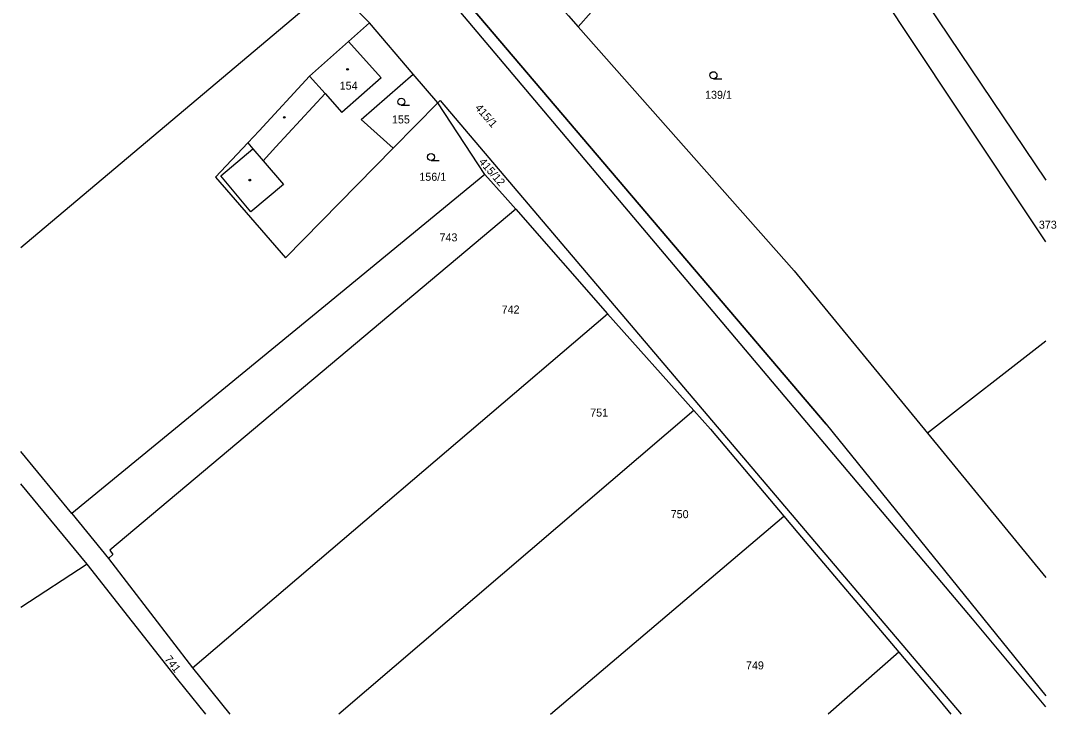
# Model space of a CAD drawing. Extents: x -504601 to -503665, y -1079870 to -1078626.
# Drawn here: x -504599.7 to -504379.8, y -1078928.2 to -1078780.8 of the extents above; entities that cross this region are included whole.
import ezdxf

# ---------------------------------------------------------------- set-up
doc = ezdxf.new("R2010")
doc.units = 0
for name, color, linetype in [('Hranice parcel', 7, 'Continuous'), ('Parcelní čísla', 7, 'Continuous'), ('Vnitřní kresba', 7, 'Continuous'), ('Vrstva 54', 7, 'Continuous'), ('Značky budov', 7, 'Continuous'), ('Značky kultur', 7, 'Continuous')]:
    doc.layers.add(name, color=color, linetype=linetype)

msp = doc.modelspace()

# ---------------------------------------------------------------- linework, layer by layer
at = {"layer": 'Hranice parcel'}
for p, q in [((-504525.66, -1078781.28), (-504530.49, -1078776.34)), ((-504599.72, -1078829.02), (-504538.29, -1078777.24)), ((-504516.36, -1078792.2), (-504525.66, -1078781.28)), ((-504483.44, -1078779.79), (-504481.39, -1078782.11)), ((-504511.18, -1078798.28), (-504516.36, -1078792.2)), ((-504520.67, -1078807.94), (-504511.18, -1078798.28)), ((-504511.18, -1078798.28), (-504510.65, -1078797.8)), ((-504501.14, -1078813.49), (-504511.18, -1078798.28)), ((-504494.6, -1078820.86), (-504475.16, -1078843.09)), ((-504563.23, -1078918.36), (-504475.16, -1078843.09)), ((-504475.16, -1078843.09), (-504456.8, -1078863.69)), ((-504382.03, -1078848.9), (-504407.21, -1078868.45)), ((-504456.8, -1078863.69), (-504532.18, -1078928.23)), ((-504407.21, -1078868.45), (-504382.03, -1078899.14)), ((-504588.84, -1078885.56), (-504599.72, -1078872.39)), ((-504588.84, -1078885.56), (-504581.08, -1078895.08)), ((-504487.22, -1078928.23), (-504437.71, -1078886.11)), ((-504581.08, -1078895.08), (-504563.23, -1078918.36)), ((-504413.27, -1078915.05), (-504428.26, -1078928.23)), ((-504563.23, -1078918.36), (-504555.31, -1078928.23))]:
    msp.add_line(p, q, dxfattribs=at)
for points in [[(-504597.09, -1078667.4), (-504514.19, -1078765.94), (-504428.7, -1078866.55), (-504382.03, -1078924.33)], [(-504382.03, -1078926.66), (-504397.6, -1078907.92), (-504520.79, -1078761.79), (-504523.08, -1078763.96), (-504532.75, -1078752.34), (-504530.29, -1078750.16), (-504595.19, -1078673.8)], [(-504382.03, -1078827.83), (-504401.66, -1078798.36), (-504417.34, -1078774.6), (-504425.36, -1078757.05)], [(-504448.13, -1078766.22), (-504448.45, -1078766.35), (-504457.1, -1078758.14), (-504465.38, -1078768.36), (-504467.53, -1078766.49), (-504481.39, -1078782.11)], [(-504417.76, -1078758.69), (-504414.04, -1078766.61), (-504407.2, -1078777.37), (-504382.03, -1078814.7)], [(-504525.66, -1078781.28), (-504530.11, -1078785.23), (-504538.39, -1078792.59), (-504549.12, -1078804.23), (-504551.53, -1078806.79), (-504558.35, -1078814.04), (-504543.52, -1078831.19), (-504520.67, -1078807.94)], [(-504481.39, -1078782.11), (-504435.49, -1078833.98), (-504407.21, -1078868.45)], [(-504520.67, -1078807.94), (-504527.41, -1078801.79), (-504516.36, -1078792.2)], [(-504510.65, -1078797.8), (-504419.66, -1078905.09), (-504400.02, -1078928.23)], [(-504501.14, -1078813.49), (-504535, -1078841.31), (-504588.84, -1078885.56)], [(-504501.14, -1078813.49), (-504496.83, -1078818.31), (-504494.6, -1078820.86)], [(-504494.6, -1078820.86), (-504580.77, -1078893.36), (-504580.15, -1078894.29), (-504581.08, -1078895.08)], [(-504456.8, -1078863.69), (-504453.26, -1078867.66), (-504437.71, -1078886.11)], [(-504585.64, -1078896.32), (-504599.72, -1078879.24)], [(-504437.71, -1078886.11), (-504434.71, -1078889.67), (-504413.27, -1078915.05)], [(-504585.64, -1078896.32), (-504599.72, -1078905.56)], [(-504560.44, -1078928.23), (-504566.37, -1078920.84), (-504585.64, -1078896.32)], [(-504413.27, -1078915.05), (-504404.47, -1078925.46), (-504402.2, -1078928.23)]]:
    msp.add_lwpolyline(points, dxfattribs=at)
at = {"layer": 'Vnitřní kresba'}
for p, q in [((-504530.11, -1078785.23), (-504523.22, -1078792.99)), ((-504538.39, -1078792.59), (-504535.08, -1078796.32)), ((-504523.22, -1078792.99), (-504531.51, -1078800.35)), ((-504545.52, -1078807.65), (-504535.08, -1078796.32)), ((-504535.08, -1078796.32), (-504531.51, -1078800.35)), ((-504551.53, -1078806.79), (-504550.45, -1078808.05)), ((-504548.25, -1078810.61), (-504545.52, -1078807.65)), ((-504557.26, -1078813.77), (-504550.45, -1078808.05)), ((-504550.45, -1078808.05), (-504548.25, -1078810.61)), ((-504548.25, -1078810.61), (-504543.94, -1078815.64)), ((-504550.83, -1078821.43), (-504557.26, -1078813.77)), ((-504543.94, -1078815.64), (-504550.83, -1078821.43))]:
    msp.add_line(p, q, dxfattribs=at)
at = {"layer": 'Vrstva 54'}
for points in [[(-504428.7, -1078866.55), (-504514.19, -1078765.94), (-504597.09, -1078667.4)], [(-504558.84, -1078682.13), (-504530.83, -1078717.69), (-504515.48, -1078737.7), (-504513.37, -1078735.66), (-504512.16, -1078737.29), (-504507.63, -1078743.89), (-504506.21, -1078745.96), (-504510.04, -1078749.73), (-504485.94, -1078776.97), (-504483.44, -1078779.79), (-504481.39, -1078782.11), (-504435.49, -1078833.98), (-504407.21, -1078868.45)]]:
    msp.add_lwpolyline(points, dxfattribs=at)
at = {"layer": 'Značky budov'}
for centre in [(-504530.32, -1078791.14), (-504543.75, -1078801.36), (-504551.08, -1078814.7)]:
    msp.add_circle(centre, 0.175, dxfattribs=at)
at = {"layer": 'Značky kultur'}
for p, q in [((-504452.63, -1078793.16), (-504450.88, -1078793.16)), ((-504518.92, -1078798.79), (-504517.17, -1078798.79)), ((-504512.6, -1078810.54), (-504510.85, -1078810.54))]:
    msp.add_line(p, q, dxfattribs=at)
for centre in [(-504452.63, -1078792.41), (-504518.92, -1078798.04), (-504512.6, -1078809.79)]:
    msp.add_circle(centre, 0.75, dxfattribs=at)

# ---------------------------------------------------------------- texts
at = {"layer": 'Parcelní čísla'}
for s, p in [('154', (-504531.99, -1078795.47)), ('139/1', (-504454.41, -1078797.41)), ('155', (-504520.89, -1078802.65)), ('156/1', (-504515.07, -1078814.84)), ('373', (-504383.53, -1078825.02)), ('743', (-504510.79, -1078827.72)), ('742', (-504497.6, -1078843.05)), ('751', (-504478.8, -1078864.96)), ('750', (-504461.7, -1078886.54)), ('749', (-504445.72, -1078918.68))]:
    msp.add_text(s, height=1.7, dxfattribs=at).set_placement(p)
for s, rotation, p in [('415/1', 311, (-504503.37, -1078799.42)), ('415/12', 311, (-504502.56, -1078810.9)), ('741', 308, (-504569.28, -1078916.53))]:
    msp.add_text(s, height=1.7, rotation=rotation, dxfattribs=at).set_placement(p)

doc.saveas('drawing.dxf')
